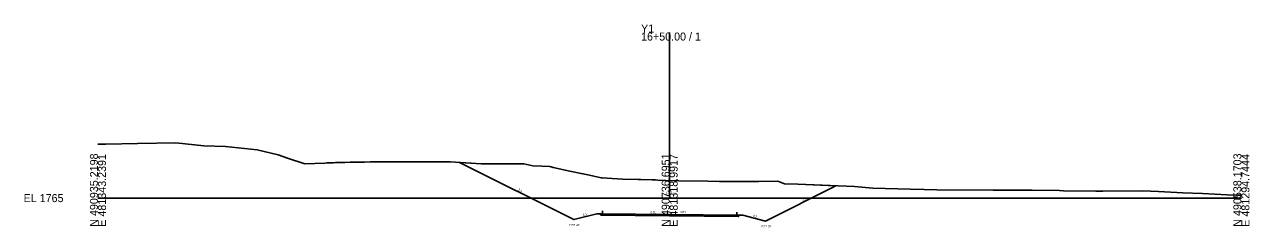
# Model space of a CAD drawing. Extents: x -26 to 403, y -10 to 6561.
# Drawn here: x -25.7 to 402.8, y 6489.7 to 6560.7 of the extents above; entities that cross this region are included whole.
import ezdxf

# ---------------------------------------------------------------- set-up
doc = ezdxf.new("R2010")
doc.units = 0
for name, color, linetype in [('Exist Cross Section Cell', 7, 'Continuous'), ('Exist XS Center Line Elevation Label', 7, 'Continuous'), ('Exist XS Ground Line', 7, 'Continuous'), ('Prop Road Sect_ Boring - Header (ID Tx)', 7, 'Continuous'), ('Prop Road Sect_ Material - Tx (Composite Desc)', 7, 'Continuous'), ('Prop XS Ditch Slope Text', 7, 'Continuous'), ('Prop XS Ditch Standard Text', 7, 'Continuous'), ('Prop XS EOT Tick Mark', 7, 'Continuous'), ('Prop XS Finish Grade', 7, 'Continuous'), ('Prop XS Finish Grade Earthwork', 7, 'Continuous'), ('Prop XS Finish Grade Pavement', 7, 'Continuous'), ('Prop XS Pvmt Edge Slope', 7, 'Continuous'), ('Prop XS SE Text', 7, 'Continuous'), ('Prop XS Side Slope Text', 7, 'Continuous'), ('Prop XS Subgrade Earthwork', 7, 'Continuous')]:
    doc.layers.add(name, color=color, linetype=linetype)

msp = doc.modelspace()

# ---------------------------------------------------------------- linework, layer by layer
at = {"layer": 'Exist Cross Section Cell'}
for p, q in [((200, 6500), (200, 6557.86)), ((0, 6500), (200, 6500)), ((200, 6500), (400, 6500))]:
    msp.add_line(p, q, dxfattribs=at)
at = {"layer": 'Exist XS Ground Line'}
msp.add_lwpolyline([(0, 6518.81), (2.78, 6518.9), (13.83, 6519.1), (27.26, 6519.29), (37.06, 6518.29), (44.58, 6517.99), (55.7, 6516.87), (63.07, 6515.09), (66.26, 6513.91), (72.36, 6511.97), (79.35, 6512.24), (80.09, 6512.29), (80.95, 6512.33), (81.43, 6512.35), (82.43, 6512.38), (83.15, 6512.4), (84.11, 6512.42), (85.69, 6512.46), (86.33, 6512.47), (88.19, 6512.52), (88.6, 6512.52), (90.73, 6512.56), (91.87, 6512.58), (93.24, 6512.6), (95.39, 6512.63), (95.77, 6512.64), (97.68, 6512.66), (98.28, 6512.67), (99.94, 6512.69), (100.81, 6512.7), (102.21, 6512.7), (103.33, 6512.71), (104.38, 6512.71), (105.39, 6512.71), (105.85, 6512.71), (106.69, 6512.71), (108.36, 6512.71), (108.9, 6512.71), (111.08, 6512.72), (112.52, 6512.73), (113.5, 6512.73), (115.89, 6512.72), (117.78, 6512.72), (118.42, 6512.72), (119.23, 6512.72), (120.89, 6512.73), (121.73, 6512.72), (122.2, 6512.72), (122.79, 6512.73), (123.25, 6512.7), (134.23, 6511.94), (135.24, 6511.94), (139.47, 6511.95), (148.98, 6511.98), (152.18, 6511.3), (155.23, 6511.21), (158.01, 6511.06), (158.57, 6510.91), (159.23, 6510.74), (165.05, 6509.44), (169.67, 6508.51), (172.01, 6508.01), (175.99, 6507.11), (176.37, 6507.09), (179.92, 6506.88), (183.59, 6506.68), (188.93, 6506.46), (189.88, 6506.45), (193.88, 6506.38), (195.08, 6506.44), (196.66, 6506.19), (198.1, 6506.23), (199.12, 6506.05), (200, 6506.07), (201.55, 6506.12), (203.23, 6505.99), (213.33, 6505.97), (217.45, 6505.76), (229.11, 6505.86), (231.13, 6505.77), (237.89, 6505.94), (240.22, 6505.04), (244.78, 6504.82), (264.67, 6504.01), (271.06, 6503.46), (284.11, 6503.08), (289, 6502.99), (293.48, 6502.85), (313.18, 6502.8), (315.52, 6502.73), (317.39, 6502.74), (326.78, 6502.74), (336.34, 6502.62), (337.8, 6502.6), (349.04, 6502.48), (351.54, 6502.46), (365.43, 6502.5), (371.04, 6502.32), (379.47, 6501.89), (386.37, 6501.61), (395.04, 6501.1), (398.45, 6501.03), (400, 6500.99)], dxfattribs=at)
at = {"layer": 'Prop Road Sect_ Boring - Header (ID Tx)'}
for points in [[(175.47, 6494.51), (175.96, 6494.02), (176.5, 6494.56)], [(224.6, 6494.04), (224.1, 6493.54), (223.55, 6494.08)]]:
    msp.add_lwpolyline(points, close=True, dxfattribs=at)
at = {"layer": 'Prop Road Sect_ Material - Tx (Composite Desc)'}
msp.add_lwpolyline([(199.99, 6493.78), (224.1, 6493.54), (224.6, 6494.04), (225.55, 6494), (233.55, 6492), (258.1, 6504.28), (244.78, 6504.82), (240.22, 6505.04), (237.89, 6505.94), (231.13, 6505.77), (229.11, 6505.86), (217.45, 6505.76), (213.33, 6505.97), (203.23, 6505.99), (201.55, 6506.12), (200, 6506.07), (199.12, 6506.05), (198.1, 6506.23), (196.66, 6506.19), (195.08, 6506.44), (193.88, 6506.38), (189.88, 6506.45), (188.93, 6506.46), (183.59, 6506.68), (179.92, 6506.88), (176.37, 6507.09), (175.99, 6507.11), (172.01, 6508.01), (169.67, 6508.51), (165.05, 6509.44), (159.23, 6510.74), (158.57, 6510.91), (158.01, 6511.06), (155.23, 6511.21), (152.18, 6511.3), (148.98, 6511.98), (139.47, 6511.95), (135.24, 6511.94), (134.23, 6511.94), (126.5, 6512.48), (166.5, 6492.48), (174.5, 6494.48), (175.47, 6494.51), (175.96, 6494.02)], close=True, dxfattribs=at)
at = {"layer": 'Prop XS EOT Tick Mark'}
for p, q in [((176.5, 6494.56), (176.5, 6495.56)), ((223.55, 6494.08), (223.55, 6495.08))]:
    msp.add_line(p, q, dxfattribs=at)
at = {"layer": 'Prop XS Finish Grade'}
for p, q in [((176.5, 6494.56), (175.47, 6494.51)), ((223.55, 6494.08), (224.6, 6494.04))]:
    msp.add_line(p, q, dxfattribs=at)
at = {"layer": 'Prop XS Finish Grade Earthwork'}
for p, q in [((166.5, 6492.48), (126.5, 6512.48)), ((233.55, 6492), (258.1, 6504.28)), ((174.5, 6494.48), (166.5, 6492.48)), ((174.5, 6494.48), (175.47, 6494.51)), ((224.6, 6494.04), (225.55, 6494)), ((225.55, 6494), (233.55, 6492))]:
    msp.add_line(p, q, dxfattribs=at)
at = {"layer": 'Prop XS Finish Grade Pavement'}
for p, q in [((176.45, 6494.56), (200, 6494.32)), ((200, 6494.32), (223.55, 6494.08))]:
    msp.add_line(p, q, dxfattribs=at)
at = {"layer": 'Prop XS Pvmt Edge Slope'}
for p, q in [((176.5, 6494.56), (175.96, 6494.02)), ((223.55, 6494.08), (224.1, 6493.54))]:
    msp.add_line(p, q, dxfattribs=at)
at = {"layer": 'Prop XS Subgrade Earthwork'}
for p, q in [((175.47, 6494.51), (175.96, 6494.02)), ((175.96, 6494.02), (199.99, 6493.78)), ((199.99, 6493.78), (224.1, 6493.54)), ((224.6, 6494.04), (224.1, 6493.54))]:
    msp.add_line(p, q, dxfattribs=at)

# ---------------------------------------------------------------- texts
at = {"layer": 'Exist Cross Section Cell'}
for s, p in [('Y1', (190, 6557.86)), ('16+50.00 / 1', (190, 6555.06)), ('EL 1765', (-26, 6498.6))]:
    msp.add_text(s, height=2.8, dxfattribs=at).set_placement(p)
for s, p in [('N 490935.2198', (0, 6490)), ('E 481343.2391', (2.8, 6490)), ('N 490736.6951', (200, 6490)), ('E 481318.9917', (202.8, 6490)), ('N 490538.1703', (400, 6490)), ('E 481294.7444', (402.8, 6490))]:
    msp.add_text(s, height=2.8, rotation=90, dxfattribs=at).set_placement(p)
at = {"layer": 'Exist XS Center Line Elevation Label'}
msp.add_text('1771.07', height=0.75, dxfattribs=at).set_placement((198.57, 6501.32))
at = {"layer": 'Prop XS Ditch Slope Text'}
for rotation, p in [(14.0362, (169.72, 6493.76)), (345.9638, (229.07, 6493.58))]:
    msp.add_text('4:1', height=0.75, rotation=rotation, dxfattribs=at).set_placement(p)
at = {"layer": 'Prop XS Ditch Standard Text'}
for s, p in [('1757.48', (164.67, 6490.23)), ('1757.00', (231.72, 6489.75))]:
    msp.add_text(s, height=0.75, dxfattribs=at).set_placement(p)
at = {"layer": 'Prop XS SE Text'}
for p in [(193.24, 6494.71), (203.64, 6494.78)]:
    msp.add_text('0.01', height=0.75, rotation=359.4271, dxfattribs=at).set_placement(p)
at = {"layer": 'Prop XS Side Slope Text'}
for rotation, p in [(333.4349, (146.95, 6502.73)), (26.5651, (246.56, 6498.93))]:
    msp.add_text('2:1', height=0.75, rotation=rotation, dxfattribs=at).set_placement(p)

doc.saveas('drawing.dxf')
